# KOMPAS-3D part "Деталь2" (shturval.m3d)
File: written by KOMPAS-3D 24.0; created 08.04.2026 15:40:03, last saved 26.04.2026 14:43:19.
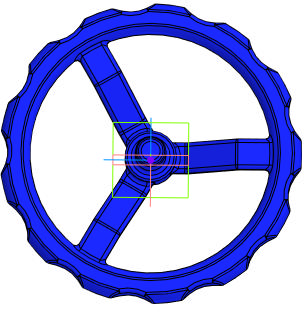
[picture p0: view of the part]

Document properties: Автор: R2D2; Полное имя файла: C:\Работа\VSO2130M-F-S Клапан запорный DN.ru\DN65\DN65\shturval.m3d

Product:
- Body: Твердое тело1  | qty 1
    Масса: 1.724044
- Part/product: Деталь2
    Масса: 1.724044
    additional columns: Типовые

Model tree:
1. Твердое тело1  (labels: Твердое тело1)
2. Масштабирование:1
3. Масштабирование : Твердое тело1
     Масштаб по оси Х = 1; Масштаб по оси Y = 1; Масштаб по оси Z = 1; Коэффициент = 1.355

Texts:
  Масштабирование : Вершина.Начало координат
